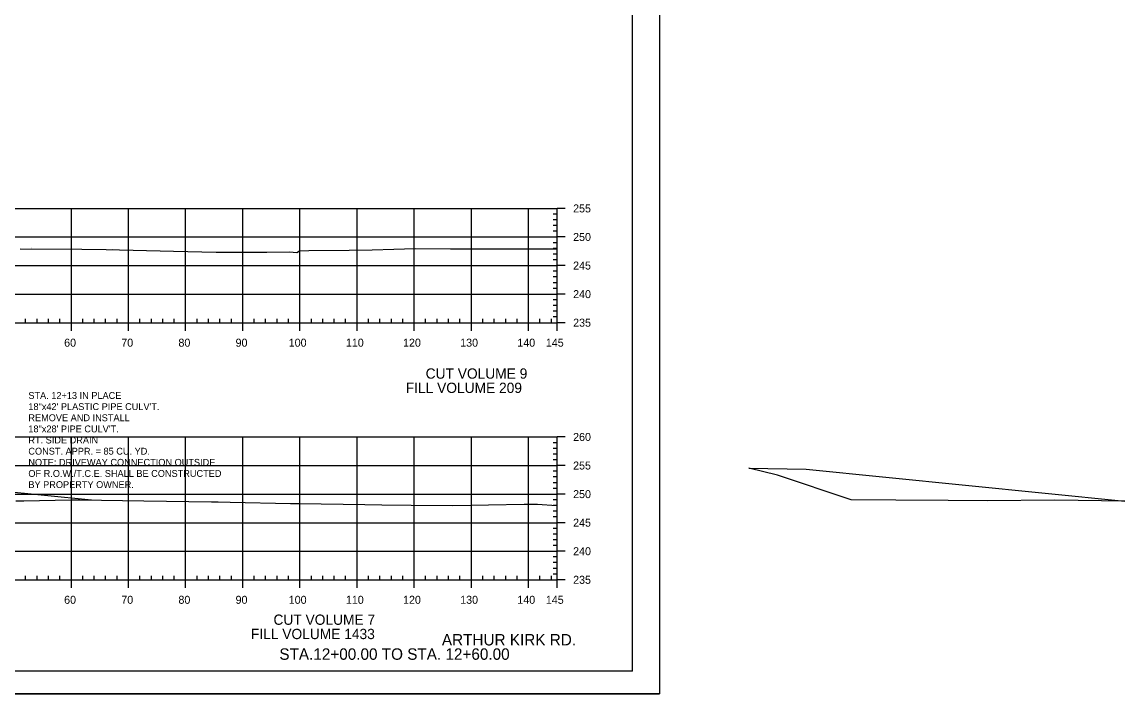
# Model space of a CAD drawing. Extents: x 1365647 to 1367999, y 387113 to 400173.
# Drawn here: x 1367806.1 to 1367999, y 387326.8 to 387444.4 of the extents above; entities that cross this region are included whole.
import ezdxf

# ---------------------------------------------------------------- set-up
doc = ezdxf.new("R2010")
doc.units = 0
for name, color, linetype in [('R_Axis', 7, 'Continuous'), ('R_Axis Annot', 7, 'Continuous'), ('R_Border', 7, 'Continuous'), ('R_Draft', 7, 'Continuous'), ('R_Drive', 7, 'Continuous'), ('R_Exist Surface', 7, 'Continuous'), ('R_Grid', 7, 'Continuous'), ('R_No Plot', 7, 'Continuous')]:
    doc.layers.add(name, color=color, linetype=linetype)

msp = doc.modelspace()

# ---------------------------------------------------------------- linework, layer by layer
at = {"layer": 'R_Axis'}
for p, q in [((1367899.68, 387391.78), (1367899.68, 387411.78)), ((1367901.08, 387411.78), (1367899.68, 387411.78)), ((1367899.68, 387410.78), (1367898.98, 387410.78)), ((1367899.68, 387409.78), (1367898.98, 387409.78)), ((1367899.68, 387408.78), (1367898.98, 387408.78)), ((1367899.68, 387407.78), (1367898.98, 387407.78)), ((1367901.08, 387406.78), (1367899.68, 387406.78)), ((1367899.68, 387405.78), (1367898.98, 387405.78)), ((1367899.68, 387404.78), (1367898.98, 387404.78)), ((1367899.68, 387403.78), (1367898.98, 387403.78)), ((1367899.68, 387402.78), (1367898.98, 387402.78)), ((1367899.68, 387400.78), (1367898.98, 387400.78)), ((1367901.08, 387401.78), (1367899.68, 387401.78)), ((1367899.68, 387399.78), (1367898.98, 387399.78)), ((1367899.68, 387398.78), (1367898.98, 387398.78)), ((1367899.68, 387397.78), (1367898.98, 387397.78)), ((1367901.08, 387396.78), (1367899.68, 387396.78)), ((1367899.68, 387395.78), (1367898.98, 387395.78)), ((1367899.68, 387394.78), (1367898.98, 387394.78)), ((1367806.68, 387391.78), (1367806.68, 387392.48)), ((1367808.68, 387391.78), (1367808.68, 387392.48)), ((1367810.68, 387391.78), (1367810.68, 387392.48)), ((1367812.68, 387391.78), (1367812.68, 387392.48)), ((1367816.68, 387391.78), (1367816.68, 387392.48)), ((1367818.68, 387391.78), (1367818.68, 387392.48)), ((1367820.68, 387391.78), (1367820.68, 387392.48)), ((1367822.68, 387391.78), (1367822.68, 387392.48)), ((1367826.68, 387391.78), (1367826.68, 387392.48)), ((1367828.68, 387391.78), (1367828.68, 387392.48)), ((1367830.68, 387391.78), (1367830.68, 387392.48)), ((1367832.68, 387391.78), (1367832.68, 387392.48)), ((1367836.68, 387391.78), (1367836.68, 387392.48)), ((1367838.68, 387391.78), (1367838.68, 387392.48)), ((1367840.68, 387391.78), (1367840.68, 387392.48)), ((1367842.68, 387391.78), (1367842.68, 387392.48)), ((1367846.68, 387391.78), (1367846.68, 387392.48)), ((1367848.68, 387391.78), (1367848.68, 387392.48)), ((1367850.68, 387391.78), (1367850.68, 387392.48)), ((1367852.68, 387391.78), (1367852.68, 387392.48)), ((1367856.68, 387391.78), (1367856.68, 387392.48)), ((1367858.68, 387391.78), (1367858.68, 387392.48)), ((1367860.68, 387391.78), (1367860.68, 387392.48)), ((1367862.68, 387391.78), (1367862.68, 387392.48)), ((1367866.68, 387391.78), (1367866.68, 387392.48)), ((1367868.68, 387391.78), (1367868.68, 387392.48)), ((1367870.68, 387391.78), (1367870.68, 387392.48)), ((1367872.68, 387391.78), (1367872.68, 387392.48)), ((1367876.68, 387391.78), (1367876.68, 387392.48)), ((1367878.68, 387391.78), (1367878.68, 387392.48)), ((1367880.68, 387391.78), (1367880.68, 387392.48)), ((1367882.68, 387391.78), (1367882.68, 387392.48)), ((1367886.68, 387391.78), (1367886.68, 387392.48)), ((1367888.68, 387391.78), (1367888.68, 387392.48)), ((1367890.68, 387391.78), (1367890.68, 387392.48)), ((1367892.68, 387391.78), (1367892.68, 387392.48)), ((1367896.68, 387391.78), (1367896.68, 387392.48)), ((1367898.68, 387391.78), (1367898.68, 387392.48)), ((1367899.68, 387393.78), (1367898.98, 387393.78)), ((1367899.68, 387392.78), (1367898.98, 387392.78)), ((1367609.68, 387391.78), (1367899.68, 387391.78)), ((1367814.68, 387390.38), (1367814.68, 387391.78)), ((1367824.68, 387390.38), (1367824.68, 387391.78)), ((1367834.68, 387390.38), (1367834.68, 387391.78)), ((1367844.68, 387390.38), (1367844.68, 387391.78)), ((1367854.68, 387390.38), (1367854.68, 387391.78)), ((1367864.68, 387390.38), (1367864.68, 387391.78)), ((1367874.68, 387390.38), (1367874.68, 387391.78)), ((1367884.68, 387390.38), (1367884.68, 387391.78)), ((1367894.68, 387390.38), (1367894.68, 387391.78)), ((1367899.68, 387390.38), (1367899.68, 387391.78)), ((1367901.08, 387391.78), (1367899.68, 387391.78)), ((1367899.68, 387346.78), (1367899.68, 387371.78)), ((1367901.08, 387371.78), (1367899.68, 387371.78)), ((1367899.68, 387370.78), (1367898.98, 387370.78)), ((1367899.68, 387369.78), (1367898.98, 387369.78)), ((1367899.68, 387368.78), (1367898.98, 387368.78)), ((1367899.68, 387367.78), (1367898.98, 387367.78)), ((1367899.68, 387365.78), (1367898.98, 387365.78)), ((1367901.08, 387366.78), (1367899.68, 387366.78)), ((1367899.68, 387364.78), (1367898.98, 387364.78)), ((1367899.68, 387363.78), (1367898.98, 387363.78)), ((1367899.68, 387362.78), (1367898.98, 387362.78)), ((1367901.08, 387361.78), (1367899.68, 387361.78)), ((1367899.68, 387360.78), (1367898.98, 387360.78)), ((1367899.68, 387359.78), (1367898.98, 387359.78)), ((1367899.68, 387358.78), (1367898.98, 387358.78)), ((1367899.68, 387357.78), (1367898.98, 387357.78)), ((1367899.68, 387355.78), (1367898.98, 387355.78)), ((1367901.08, 387356.78), (1367899.68, 387356.78)), ((1367899.68, 387354.78), (1367898.98, 387354.78)), ((1367899.68, 387353.78), (1367898.98, 387353.78)), ((1367899.68, 387352.78), (1367898.98, 387352.78)), ((1367899.68, 387350.78), (1367898.98, 387350.78)), ((1367901.08, 387351.78), (1367899.68, 387351.78)), ((1367899.68, 387349.78), (1367898.98, 387349.78)), ((1367899.68, 387348.78), (1367898.98, 387348.78)), ((1367609.68, 387346.78), (1367899.68, 387346.78)), ((1367806.68, 387346.78), (1367806.68, 387347.48)), ((1367808.68, 387346.78), (1367808.68, 387347.48)), ((1367810.68, 387346.78), (1367810.68, 387347.48)), ((1367812.68, 387346.78), (1367812.68, 387347.48)), ((1367814.68, 387345.38), (1367814.68, 387346.78)), ((1367816.68, 387346.78), (1367816.68, 387347.48)), ((1367818.68, 387346.78), (1367818.68, 387347.48)), ((1367820.68, 387346.78), (1367820.68, 387347.48)), ((1367822.68, 387346.78), (1367822.68, 387347.48)), ((1367824.68, 387345.38), (1367824.68, 387346.78)), ((1367826.68, 387346.78), (1367826.68, 387347.48)), ((1367828.68, 387346.78), (1367828.68, 387347.48)), ((1367830.68, 387346.78), (1367830.68, 387347.48)), ((1367832.68, 387346.78), (1367832.68, 387347.48)), ((1367834.68, 387345.38), (1367834.68, 387346.78)), ((1367836.68, 387346.78), (1367836.68, 387347.48)), ((1367838.68, 387346.78), (1367838.68, 387347.48)), ((1367840.68, 387346.78), (1367840.68, 387347.48)), ((1367842.68, 387346.78), (1367842.68, 387347.48)), ((1367844.68, 387345.38), (1367844.68, 387346.78)), ((1367846.68, 387346.78), (1367846.68, 387347.48)), ((1367848.68, 387346.78), (1367848.68, 387347.48)), ((1367850.68, 387346.78), (1367850.68, 387347.48)), ((1367852.68, 387346.78), (1367852.68, 387347.48)), ((1367854.68, 387345.38), (1367854.68, 387346.78)), ((1367856.68, 387346.78), (1367856.68, 387347.48)), ((1367858.68, 387346.78), (1367858.68, 387347.48)), ((1367860.68, 387346.78), (1367860.68, 387347.48)), ((1367862.68, 387346.78), (1367862.68, 387347.48)), ((1367864.68, 387345.38), (1367864.68, 387346.78)), ((1367866.68, 387346.78), (1367866.68, 387347.48)), ((1367868.68, 387346.78), (1367868.68, 387347.48)), ((1367870.68, 387346.78), (1367870.68, 387347.48)), ((1367872.68, 387346.78), (1367872.68, 387347.48)), ((1367874.68, 387345.38), (1367874.68, 387346.78)), ((1367876.68, 387346.78), (1367876.68, 387347.48)), ((1367878.68, 387346.78), (1367878.68, 387347.48)), ((1367880.68, 387346.78), (1367880.68, 387347.48)), ((1367882.68, 387346.78), (1367882.68, 387347.48)), ((1367884.68, 387345.38), (1367884.68, 387346.78)), ((1367886.68, 387346.78), (1367886.68, 387347.48)), ((1367888.68, 387346.78), (1367888.68, 387347.48)), ((1367890.68, 387346.78), (1367890.68, 387347.48)), ((1367892.68, 387346.78), (1367892.68, 387347.48)), ((1367894.68, 387345.38), (1367894.68, 387346.78)), ((1367896.68, 387346.78), (1367896.68, 387347.48)), ((1367898.68, 387346.78), (1367898.68, 387347.48)), ((1367899.68, 387347.78), (1367898.98, 387347.78)), ((1367899.68, 387345.38), (1367899.68, 387346.78)), ((1367901.08, 387346.78), (1367899.68, 387346.78))]:
    msp.add_line(p, q, dxfattribs=at)
at = {"layer": 'R_Border'}
for q in [(1367912.86, 387536.24), (1367596.68, 387330.78)]:
    msp.add_line((1367912.86, 387330.78), q, dxfattribs=at)
at = {"layer": 'R_Drive'}
msp.add_lwpolyline([(1367933.24, 387366.33), (1367943.24, 387366.13), (1367999.04, 387360.54), (1367986.77, 387360.72), (1367974.92, 387360.61), (1367968.12, 387360.67), (1367958.93, 387360.73), (1367951.13, 387360.79), (1367938.24, 387365.08)], close=True, dxfattribs=at)
at = {"layer": 'R_Exist Surface'}
for points in [[(1367805.73, 387404.71), (1367816.54, 387404.66), (1367820.8, 387404.61), (1367832.53, 387404.3), (1367840.03, 387404.15), (1367848.9, 387404.12), (1367852.86, 387404.17), (1367854.16, 387404.06), (1367854.58, 387404.35), (1367856.22, 387404.44), (1367863.31, 387404.45), (1367867.32, 387404.53), (1367871.1, 387404.63), (1367874.87, 387404.74), (1367881.03, 387404.71), (1367881.18, 387404.71), (1367881.22, 387404.71), (1367883.21, 387404.71), (1367896.9, 387404.72), (1367897.88, 387404.7), (1367899.62, 387404.72), (1367899.68, 387404.72)], [(1367804.97, 387360.59), (1367806.35, 387360.61), (1367814.58, 387360.77), (1367815.67, 387360.76), (1367816.24, 387360.75), (1367827.34, 387360.58), (1367839.18, 387360.44), (1367840.36, 387360.41), (1367842.47, 387360.37), (1367853.05, 387360.16), (1367854.58, 387360.14), (1367866.05, 387359.97), (1367869.03, 387359.92), (1367874.13, 387359.86), (1367881.46, 387359.81), (1367893.9, 387360.01), (1367895.51, 387360), (1367896.25, 387360.01), (1367899.58, 387359.76), (1367899.68, 387359.76)]]:
    msp.add_lwpolyline(points, dxfattribs=at)
at = {"layer": 'R_Grid'}
for p, q in [((1367609.68, 387411.78), (1367899.68, 387411.78)), ((1367814.68, 387391.78), (1367814.68, 387411.78)), ((1367824.68, 387391.78), (1367824.68, 387411.78)), ((1367834.68, 387391.78), (1367834.68, 387411.78)), ((1367844.68, 387391.78), (1367844.68, 387411.78)), ((1367854.68, 387391.78), (1367854.68, 387411.78)), ((1367864.68, 387391.78), (1367864.68, 387411.78)), ((1367874.68, 387391.78), (1367874.68, 387411.78)), ((1367884.68, 387391.78), (1367884.68, 387411.78)), ((1367894.68, 387391.78), (1367894.68, 387411.78)), ((1367899.68, 387391.78), (1367899.68, 387411.78)), ((1367609.68, 387406.78), (1367899.68, 387406.78)), ((1367609.68, 387401.78), (1367899.68, 387401.78)), ((1367609.68, 387396.78), (1367899.68, 387396.78)), ((1367609.68, 387391.78), (1367899.68, 387391.78)), ((1367609.68, 387371.78), (1367899.68, 387371.78)), ((1367609.68, 387371.78), (1367899.68, 387371.78)), ((1367814.68, 387346.78), (1367814.68, 387371.78)), ((1367814.68, 387346.78), (1367814.68, 387371.78)), ((1367824.68, 387346.78), (1367824.68, 387371.78)), ((1367824.68, 387346.78), (1367824.68, 387371.78)), ((1367834.68, 387346.78), (1367834.68, 387371.78)), ((1367834.68, 387346.78), (1367834.68, 387371.78)), ((1367844.68, 387346.78), (1367844.68, 387371.78)), ((1367844.68, 387346.78), (1367844.68, 387371.78)), ((1367854.68, 387346.78), (1367854.68, 387371.78)), ((1367854.68, 387346.78), (1367854.68, 387371.78)), ((1367864.68, 387346.78), (1367864.68, 387371.78)), ((1367864.68, 387346.78), (1367864.68, 387371.78)), ((1367874.68, 387346.78), (1367874.68, 387371.78)), ((1367874.68, 387346.78), (1367874.68, 387371.78)), ((1367884.68, 387346.78), (1367884.68, 387371.78)), ((1367884.68, 387346.78), (1367884.68, 387371.78)), ((1367894.68, 387346.78), (1367894.68, 387371.78)), ((1367894.68, 387346.78), (1367894.68, 387371.78)), ((1367899.68, 387346.78), (1367899.68, 387371.78)), ((1367899.68, 387346.78), (1367899.68, 387371.78)), ((1367609.68, 387366.78), (1367899.68, 387366.78)), ((1367609.68, 387366.78), (1367899.68, 387366.78)), ((1367609.68, 387361.78), (1367899.68, 387361.78)), ((1367609.68, 387361.78), (1367899.68, 387361.78)), ((1367609.68, 387356.78), (1367899.68, 387356.78)), ((1367609.68, 387356.78), (1367899.68, 387356.78)), ((1367609.68, 387351.78), (1367899.68, 387351.78)), ((1367609.68, 387351.78), (1367899.68, 387351.78)), ((1367609.68, 387346.78), (1367899.68, 387346.78)), ((1367609.68, 387346.78), (1367899.68, 387346.78))]:
    msp.add_line(p, q, dxfattribs=at)
at = {"layer": 'R_No Plot'}
for p, q in [((1367818.2, 387360.72), (1367774.68, 387365.08)), ((1367584.28, 387326.81), (1367917.62, 387326.81))]:
    msp.add_line(p, q, dxfattribs=at)
msp.add_lwpolyline([(1367584.28, 387540.14), (1367917.62, 387540.14), (1367917.62, 387326.8), (1367584.28, 387326.8)], close=True, dxfattribs=at)

# ---------------------------------------------------------------- texts
at = {"layer": 'R_Axis Annot'}
for s, height, p in [('255', 1.4, (1367902.48, 387411.08)), ('250', 1.4, (1367902.48, 387406.08)), ('245', 1.4, (1367902.48, 387401.08)), ('240', 1.4, (1367902.48, 387396.08)), ('235', 1.4, (1367902.48, 387391.08)), ('60', 1.4, (1367813.42, 387387.58)), ('70', 1.4, (1367823.42, 387387.58)), ('80', 1.4, (1367833.42, 387387.58)), ('90', 1.4, (1367843.42, 387387.58)), ('100', 1.4, (1367852.72, 387387.58)), ('110', 1.4, (1367862.72, 387387.58)), ('120', 1.4, (1367872.72, 387387.58)), ('130', 1.4, (1367882.72, 387387.58)), ('140', 1.4, (1367892.72, 387387.58)), ('145', 1.4, (1367897.71, 387387.58)), ('CUT VOLUME 9', 1.8, (1367876.68, 387381.98)), ('FILL VOLUME 209', 1.8, (1367873.2, 387379.48)), ('260', 1.4, (1367902.48, 387371.08)), ('255', 1.4, (1367902.48, 387366.08)), ('250', 1.4, (1367902.48, 387361.08)), ('245', 1.4, (1367902.48, 387356.08)), ('240', 1.4, (1367902.48, 387351.08)), ('235', 1.4, (1367902.48, 387346.08)), ('60', 1.4, (1367813.42, 387342.58)), ('70', 1.4, (1367823.42, 387342.58)), ('80', 1.4, (1367833.42, 387342.58)), ('90', 1.4, (1367843.42, 387342.58)), ('100', 1.4, (1367852.72, 387342.58)), ('110', 1.4, (1367862.72, 387342.58)), ('120', 1.4, (1367872.72, 387342.58)), ('130', 1.4, (1367882.72, 387342.58)), ('140', 1.4, (1367892.72, 387342.58)), ('145', 1.4, (1367897.71, 387342.58)), ('CUT VOLUME 7', 1.8, (1367850.05, 387338.9)), ('FILL VOLUME 1433', 1.8, (1367846.11, 387336.4))]:
    msp.add_text(s, height=height, dxfattribs=at).set_placement(p)
at = {"layer": 'R_Draft'}
for s, p in [('STA. 12+13 IN PLACE', (1367807.16, 387378.44)), ('18"x42\' PLASTIC PIPE CULV\'T.', (1367807.16, 387376.49)), ('REMOVE AND INSTALL ', (1367807.16, 387374.54)), ('18"x28\' PIPE CULV\'T.', (1367807.16, 387372.59)), ('RT. SIDE DRAIN', (1367807.16, 387370.64)), ('CONST. APPR. = 85 CU. YD.', (1367807.16, 387368.69)), ('NOTE: DRIVEWAY CONNECTION OUTSIDE ', (1367807.16, 387366.74)), ('OF R.O.W./T.C.E. SHALL BE CONSTRUCTED ', (1367807.16, 387364.79)), ('BY PROPERTY OWNER.', (1367807.16, 387362.84))]:
    msp.add_text(s, height=1.2, rotation=360, dxfattribs=at).set_placement(p)
for s, p in [('ARTHUR KIRK RD.', (1367879.52, 387335.29)), ('STA.12+00.00 TO STA. 12+60.00', (1367851.08, 387332.78))]:
    msp.add_text(s, height=2, dxfattribs=at).set_placement(p)
at = {"layer": 'R_No Plot'}
for p in [(1367807.67, 387404.81), (1367821.8, 387404.6), (1367827.62, 387404.41), (1367844.38, 387404.1), (1367856.18, 387404.39), (1367871.05, 387404.58), (1367881.18, 387404.66), (1367896.86, 387404.67), (1367814.54, 387360.72), (1367839.13, 387360.38), (1367874.09, 387359.81), (1367895.46, 387359.95), (1367899.54, 387359.71)]:
    msp.add_text('+', height=0.1, dxfattribs=at).set_placement(p)

doc.saveas('drawing.dxf')
